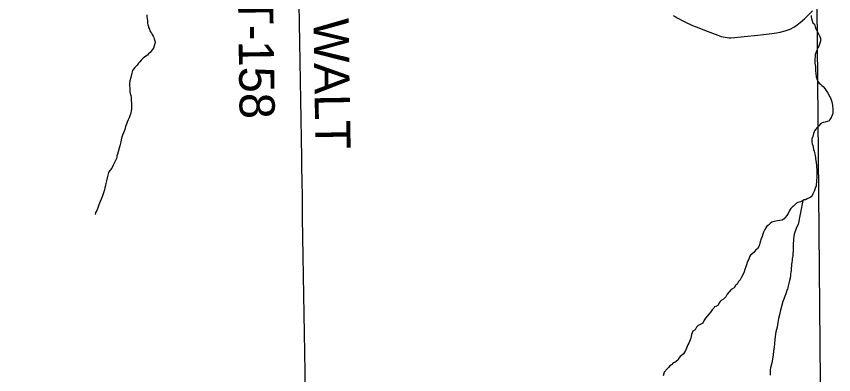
# Model space of a CAD drawing. Extents: x 103424 to 286016, y 38711 to 110967.
# Drawn here: x 112838 to 119854, y 63924 to 66995 of the extents above; entities that cross this region are included whole.
import ezdxf

# ---------------------------------------------------------------- set-up
doc = ezdxf.new("R2010")
doc.units = 0
for name, color, linetype in [('GM_X_Corporation', 7, 'Continuous'), ('GM_X_County_Road', 7, 'Continuous'), ('GM_X_Minor_River', 7, 'Continuous'), ('GM_X_Township_Road', 7, 'Continuous'), ('GM_X_Township_Road_Text', 7, 'Continuous')]:
    doc.layers.add(name, color=color, linetype=linetype)

msp = doc.modelspace()

# ---------------------------------------------------------------- linework, layer by layer
at = {"layer": 'GM_X_Corporation'}
for points in [[(119747.3, 63220.6), (119711.4, 67089.1), (119699.4, 68185.2), (119697.8, 68222.7), (119697.6, 68351.3), (119691.9, 68458.1), (119686.6, 68980.3), (119689.3, 69057.6), (119689.9, 69111.8), (119690.7, 69193.8), (119690.7, 69692.5), (119693.5, 70192.5), (119690.7, 70601.3), (119688.2, 70990.2), (120142.1, 70987.1), (120536.9, 70987), (120770.1, 70987.9), (120904.4, 70988.4), (125782.9, 71007.1), (127353.3, 71034.4)], [(119747.3, 63220.6), (119711.4, 67089.1), (119699.4, 68185.2), (119697.8, 68222.7), (119697.6, 68351.3), (119691.9, 68458.1), (119686.6, 68980.3), (119689.3, 69057.6), (119689.9, 69111.8), (119690.7, 69193.8), (119690.7, 69692.5), (119693.5, 70192.5), (119690.7, 70601.3), (119688.2, 70990.2), (117946.9, 70934.9), (117928.9, 70934.4), (107977, 70917.3), (103423.7, 70904.9), (103423.7, 43132.7)]]:
    msp.add_lwpolyline(points, dxfattribs=at)
at = {"layer": 'GM_X_County_Road'}
msp.add_lwpolyline([(118476.6, 67004.3), (118494, 66993.8), (118511.1, 66983.5), (118528.7, 66973.6), (118546.3, 66963.9), (118564.1, 66954.6), (118582.3, 66945.5), (118600.4, 66936.8), (118618.5, 66928.4), (118637.1, 66920.4), (118655.7, 66912.6), (118674.4, 66905.2), (118767.2, 66869.3), (118860.1, 66833.4), (118872.9, 66828.7), (118889.1, 66823.8), (118905.4, 66819.6), (118921.8, 66816.3), (118938.6, 66813.9), (118955.3, 66812.4), (118972.1, 66811.8), (119005.9, 66813.1), (119084.9, 66821.6), (119204.2, 66835.6), (119323.5, 66849.5), (119362.9, 66854.2), (119393.9, 66860.4), (119437.4, 66871.3), (119481.4, 66886.8), (119510.9, 66902.9), (119528, 66913.2), (119567.3, 66943.2), (119603.6, 66973.8), (119672.6, 67044.1)], dxfattribs=at)
at = {"layer": 'GM_X_Minor_River'}
for points in [[(113957.4, 67007.5), (113957.7, 66991.4), (113960, 66975.2), (113962.2, 66961.1), (113964.5, 66949.1)], [(113964.5, 66949.1), (113964.6, 66939), (113966.9, 66922.8), (113971.2, 66908.8), (113973.4, 66898.7), (113979.7, 66884.6), (113983.9, 66872.6), (113990.1, 66862.6), (113996.4, 66850.6), (114002.6, 66840.6), (114013, 66824.6), (114017.2, 66814.6), (114019.4, 66802.5), (114025.7, 66786.4), (114030, 66772.3), (114014.6, 66723.6), (114004.8, 66709.3), (113994.9, 66697), (113985, 66686.8), (113973.1, 66674.4), (113963.2, 66664.2), (113949.2, 66653.8), (113937.3, 66645.6), (113927.3, 66637.3), (113909.5, 66618.8), (113897.6, 66604.5), (113885.7, 66594.2), (113873.8, 66577.8), (113856, 66557.3), (113844.1, 66543), (113834.3, 66530.7), (113828.6, 66508.4), (113821.1, 66471.9), (113811.5, 66441.5), (113807.9, 66417.2), (113808.2, 66399), (113810.5, 66382.9), (113810.8, 66366.7), (113813.1, 66348.6), (113815.4, 66334.4), (113819.7, 66318.4), (113822, 66300.2), (113822.2, 66286.1), (113822.5, 66269.9), (113824.7, 66255.8), (113827, 66243.7), (113827.2, 66229.6), (113827.4, 66219.5), (113825.7, 66201.3), (113823.9, 66187.1), (113820.2, 66166.8), (113812.5, 66142.5), (113804.7, 66126.2), (113797, 66107.9), (113789.2, 66089.6), (113783.4, 66071.3), (113775.7, 66050.9), (113768.1, 66024.6), (113758.4, 65998.1), (113748.7, 65975.8), (113741.1, 65951.4), (113733.5, 65921), (113726, 65886.5), (113705, 65813.4), (113701.2, 65799.2), (113699.4, 65787.1), (113697.6, 65776.9), (113689.8, 65760.6), (113678, 65738.2), (113668.3, 65719.9), (113656.6, 65695.4), (113640.8, 65675), (113629, 65656.6), (113623.3, 65634.3), (113617.6, 65610), (113612, 65585.6), (113606.3, 65563.3), (113602.6, 65545.1), (113596.9, 65524.8), (113593.1, 65508.5), (113585.5, 65482.1), (113577.8, 65457.8), (113568.1, 65435.4), (113556.4, 65408.9), (113546.8, 65380.5), (113537.2, 65354.1), (113527.5, 65331.7), (113519.7, 65315.4), (113517.7, 65313.3), (113513.9, 65297.1)], [(119661.9, 67002.2), (119662.1, 66990.1), (119664.3, 66978), (119668.7, 66957.9), (119675, 66939.8), (119689.4, 66927.9), (119691.6, 66915.9), (119695.8, 66905.8), (119702.1, 66887.7), (119708.4, 66873.7), (119720.9, 66851.7), (119729.3, 66833.6), (119735.5, 66821.6), (119739.8, 66805.5), (119742.2, 66783.3), (119736.5, 66767.1), (119730.7, 66748.8), (119724.9, 66734.6), (119719, 66724.4), (119713.1, 66714.2), (119709.3, 66704), (119703.4, 66693.8), (119699.5, 66681.6), (119695.7, 66667.4), (119694, 66651.2), (119692.3, 66635), (119692.6, 66612.8), (119692.9, 66594.6), (119695.2, 66578.5), (119697.5, 66564.4), (119697.7, 66548.3), (119698, 66534.1), (119698.2, 66524), (119700.4, 66511.9), (119700.6, 66497.8), (119702.8, 66485.7), (119705, 66475.7), (119709.3, 66459.6), (119715.6, 66445.5), (119721.9, 66433.5), (119730.1, 66423.5), (119740.4, 66413.6), (119752.6, 66403.7), (119764.9, 66393.8), (119779.3, 66375.9), (119787.6, 66363.9), (119795.9, 66351.9), (119802.1, 66341.9), (119812.5, 66323.9), (119818.8, 66307.8), (119827.1, 66295.8), (119833.4, 66279.8), (119837.7, 66263.7), (119842, 66249.6), (119844.2, 66235.5), (119847, 66193.1), (119847.2, 66181), (119845.5, 66162.8), (119839.7, 66148.6), (119831.9, 66128.2), (119822.1, 66109.9), (119816.2, 66099.7), (119800.2, 66093.4), (119782.1, 66089), (119764, 66084.7), (119754, 66082.5), (119744, 66076.3), (119726.1, 66057.8), (119710.3, 66039.4), (119700.4, 66027.1), (119690.5, 66014.8), (119686.7, 66004.6), (119680.9, 65990.4), (119675.2, 65966), (119667.5, 65945.7), (119665.7, 65931.5), (119665.9, 65919.4), (119670.3, 65901.3), (119674.5, 65889.3), (119676.7, 65875.1)], [(119676.7, 65875.1), (119681.1, 65855), (119687.4, 65841), (119689.6, 65828.9), (119691.8, 65816.8), (119694.1, 65800.7), (119698.4, 65786.6), (119698.6, 65774.5), (119700.9, 65758.4), (119703.2, 65740.2), (119705.6, 65720.1), (119705.9, 65701.9), (119708.2, 65681.7), (119708.6, 65661.5), (119708.9, 65643.4), (119709.1, 65633.2), (119709.3, 65621.1), (119707.8, 65586.8), (119706, 65572.6), (119704.3, 65556.4), (119702.5, 65540.2), (119698.7, 65530), (119692.9, 65511.8), (119689.1, 65501.6), (119681.3, 65485.3), (119675.4, 65473.1), (119669.6, 65460.9), (119661.7, 65448.6), (119647.7, 65438.3), (119625.7, 65429.8), (119611.7, 65423.6), (119601.6, 65423.4), (119587.6, 65415.1), (119569.6, 65406.7), (119547.5, 65400.3), (119535.5, 65394), (119525.5, 65385.8), (119509.7, 65369.4), (119499.7, 65361.1), (119485.8, 65348.8), (119474, 65332.4), (119462.3, 65305.9), (119450.5, 65287.6), (119438.7, 65271.2), (119428.8, 65261), (119412.8, 65248.6), (119390.7, 65244.2), (119370.5, 65241.8), (119332.3, 65235.1), (119322.3, 65230.9), (119308.4, 65220.6), (119294.5, 65206.2), (119280.5, 65195.9), (119270.7, 65181.6), (119262.8, 65167.3), (119256.9, 65157.1), (119251.1, 65144.9), (119245.3, 65128.6), (119239.6, 65108.3), (119233.8, 65094.1), (119229.9, 65083.9), (119226.2, 65067.7), (119220.4, 65051.5), (119214.7, 65029.1), (119201, 65002.7), (119187, 64994.3), (119169.3, 64971.8), (119151.3, 64957.4), (119139.4, 64949.1), (119131.6, 64932.8), (119125.8, 64914.6), (119118, 64900.3), (119112.2, 64884), (119106.5, 64865.7), (119100.7, 64847.5), (119091, 64825.1), (119085.3, 64804.8), (119075.6, 64780.4), (119061.8, 64759.9), (119052.1, 64735.5), (119036.2, 64721.1), (119024.5, 64700.7), (119010.6, 64688.4), (118998.8, 64668), (118974.8, 64653.5), (118939.2, 64612.5), (118929.4, 64592.1), (118907.6, 64571.5), (118889.6, 64559.1), (118879.7, 64550.9), (118871.8, 64540.7), (118862, 64520.3), (118842.1, 64507.8), (118830, 64505.6), (118826.2, 64493.4), (118812.3, 64479.1), (118798.4, 64462.7), (118784.6, 64444.3), (118766.8, 64423.8), (118755, 64407.4), (118743.1, 64391.1)], [(119589.3, 65416.1), (119548.6, 65212.4), (119538.9, 65192), (119531.1, 65175.8), (119527.3, 65159.5), (119521.5, 65145.3), (119515.7, 65127), (119512, 65108.8), (119510.3, 65090.6), (119508.7, 65068.3), (119506.9, 65054.1), (119507, 65044), (119507.3, 65027.9), (119507.7, 65005.7), (119506.1, 64983.4), (119502.4, 64963.2), (119502.7, 64942.9), (119499, 64920.7), (119497.3, 64902.5), (119495.6, 64884.2), (119491.8, 64870), (119492.1, 64853.9), (119490.3, 64839.7), (119488.5, 64827.6), (119488.7, 64817.5), (119486.9, 64803.3), (119483, 64791.1), (119483.3, 64772.9), (119479.7, 64750.6), (119476, 64730.4), (119470.3, 64708.1), (119464.6, 64685.7), (119460.9, 64669.5), (119457, 64657.3), (119453.2, 64647.2), (119449.3, 64637), (119443.6, 64616.7), (119433.8, 64596.3), (119426.2, 64572), (119418.5, 64551.7), (119395.7, 64466.4), (119388.1, 64436), (119380.5, 64405.6), (119375.1, 64371.1), (119367.7, 64330.6), (119358.2, 64292.1), (119352.8, 64251.6), (119349.3, 64225.2), (119344.3, 64158.5), (119338.8, 64128.1), (119335.4, 64091.7), (119324.4, 64024.8), (119313, 63982.2), (119309.2, 63964), (119307.7, 63937.7), (119308, 63919.5)], [(118743.1, 64391.1), (118729.4, 64364.6), (118707.4, 64354.1), (118691.5, 64343.8), (118677.5, 64331.4), (118663.8, 64306.9), (118643.8, 64296.5), (118634.2, 64268.1), (118630.4, 64253.9), (118626.7, 64235.6), (118617, 64209.2), (118609.2, 64192.9), (118603.4, 64180.7), (118597.6, 64164.4), (118589.8, 64150.2), (118582, 64129.8), (118564.3, 64103.3), (118548.5, 64086.9), (118536.5, 64078.6), (118528.6, 64068.3), (118514.8, 64047.9), (118490.9, 64029.3), (118476.9, 64025.1), (118461, 64008.6), (118447, 63998.3), (118437.2, 63986), (118423.2, 63973.7), (118397.5, 63945), (118389.9, 63914.5)]]:
    msp.add_lwpolyline(points, dxfattribs=at)
at = {"layer": 'GM_X_Township_Road'}
msp.add_lwpolyline([(115318.3, 63783.5), (115315.8, 63948.5), (115313.2, 64113.5), (115310.7, 64278.6), (115308.2, 64443.6), (115305.6, 64608.6), (115303.1, 64773.7), (115300.5, 64938.7), (115298, 65103.7), (115295.4, 65268.8), (115292.8, 65433.8), (115290.3, 65598.8), (115288.9, 65690.9), (115287.4, 65782.9), (115284.9, 65948), (115282.3, 66113), (115279.7, 66278), (115277.1, 66443.1), (115274.6, 66608.1), (115272, 66773.1), (115269.4, 66938.2), (115266.8, 67103.2)], dxfattribs=at)

# ---------------------------------------------------------------- texts
at = {"layer": 'GM_X_Township_Road_Text'}
for s, rotation, p in [('T-158', 270.84069, (114740, 67168.3)), ('WALT', 270.95036, (115387.2, 66976.6))]:
    msp.add_text(s, height=301.87, rotation=rotation, dxfattribs=at).set_placement(p)

doc.saveas('drawing.dxf')
